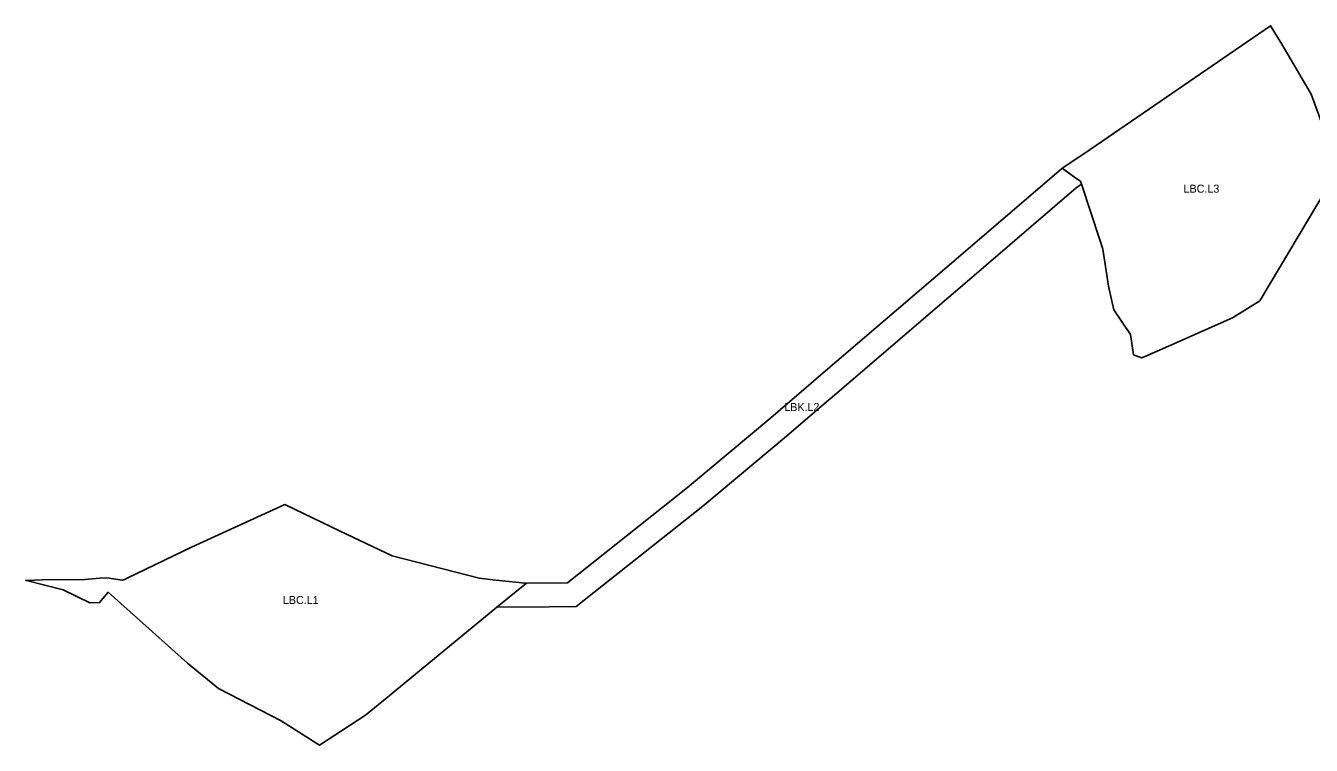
# Model space of a CAD drawing. Extents: x -450188 to -432919, y -1130252 to -1121189.
# Drawn here: x -439083 to -437477, y -1122136 to -1121237 of the extents above; entities that cross this region are included whole.
import ezdxf

# ---------------------------------------------------------------- set-up
doc = ezdxf.new("R2010")
doc.units = 0
for name, color, linetype in [('Vrstva 32', 7, 'Continuous'), ('Vrstva 33', 7, 'Continuous'), ('Vrstva 36', 7, 'Continuous')]:
    doc.layers.add(name, color=color, linetype=linetype)

msp = doc.modelspace()

# ---------------------------------------------------------------- linework, layer by layer
at = {"layer": 'Vrstva 32'}
for p, q in [((-438464, -1121938.6), (-438494.7, -1121963.7)), ((-438460.3, -1121935.6), (-438464, -1121938.6))]:
    msp.add_line(p, q, dxfattribs=at)
for points in [[(-437770.1, -1121428.3), (-437788.4, -1121415.2), (-437760.2, -1121396.4), (-437528.3, -1121237.1), (-437514.3, -1121260.3), (-437477.4, -1121322.7), (-437477.4, -1121322.8)], [(-437477.4, -1121322.8), (-437466.8, -1121352.1), (-437443.5, -1121416), (-437541.7, -1121580.8), (-437575.9, -1121602.1), (-437641.5, -1121631), (-437684, -1121649.8), (-437689.3, -1121652.1), (-437699.4, -1121648.2), (-437703.4, -1121622.9), (-437724.2, -1121592), (-437730.9, -1121562.3), (-437732.1, -1121554.2), (-437737.6, -1121516.2), (-437741.5, -1121504.5), (-437764.5, -1121435)], [(-437764.5, -1121435), (-437765.7, -1121431.4), (-437770.1, -1121428.3)], [(-438494.7, -1121963.7), (-438631.8, -1122076.2), (-438659, -1122098.6), (-438716.2, -1122136.1), (-438719.5, -1122134), (-438764.1, -1122105.7), (-438842.3, -1122065.1), (-438881.3, -1122033.3), (-438937.1, -1121983.5), (-438980.4, -1121944.8), (-438991, -1121957.9), (-439003.3, -1121958.1), (-439036.5, -1121942), (-439082.5, -1121930.4), (-439083.3, -1121930.2), (-439082.4, -1121930.2), (-439052.8, -1121929), (-439013.9, -1121929.2), (-438991.1, -1121927.2), (-438981.9, -1121926.9), (-438962.2, -1121930), (-438960.1, -1121929), (-438955.8, -1121926.9), (-438876.4, -1121888.6), (-438759.8, -1121835.3), (-438690.3, -1121868.4), (-438625.6, -1121899.6), (-438516.8, -1121927.4), (-438499.6, -1121929.3), (-438467.1, -1121932.8), (-438461, -1121933.5), (-438457.7, -1121933.4), (-438460.3, -1121935.6)]]:
    msp.add_lwpolyline(points, dxfattribs=at)
at = {"layer": 'Vrstva 33'}
for points in [[(-437764.5, -1121435), (-437767.1, -1121436.8), (-437770.9, -1121439.5), (-437910.3, -1121559), (-437950.2, -1121593.3), (-438076.1, -1121701), (-438083, -1121707), (-438133.1, -1121749.8), (-438237.6, -1121837.3), (-438395.8, -1121962.9), (-438429.3, -1121963.2), (-438494.7, -1121963.7), (-438464, -1121938.6), (-438460.3, -1121935.6), (-438457.7, -1121933.4), (-438406.4, -1121933), (-438256.5, -1121814), (-438152.5, -1121726.9), (-438102.6, -1121684.2), (-438095.7, -1121678.2), (-437969.7, -1121570.5), (-437929.9, -1121536.3), (-437789.4, -1121415.8), (-437788.4, -1121415.2), (-437784.8, -1121417.9), (-437770.1, -1121428.3)], [(-437770.1, -1121428.3), (-437765.7, -1121431.4), (-437764.5, -1121435)]]:
    msp.add_lwpolyline(points, dxfattribs=at)

# ---------------------------------------------------------------- texts
at = {"layer": 'Vrstva 36'}
for s, p in [('LBC.L3', (-437636.9, -1121445.7)), ('LBK.L2', (-438135.7, -1121718.5)), ('LBC.L1', (-438762, -1121959.6))]:
    msp.add_text(s, height=10, dxfattribs=at).set_placement(p)

doc.saveas('drawing.dxf')
